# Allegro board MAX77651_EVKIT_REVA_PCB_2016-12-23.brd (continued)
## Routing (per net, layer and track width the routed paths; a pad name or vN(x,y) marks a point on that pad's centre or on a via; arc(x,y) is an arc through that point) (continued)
VBATT: length 4.3
  TOP w0.152: 46.89,40.22 U1.E3
  TOP w0.254: 46.89,40.22 46.89,40.14 46.37,39.61 46.23,39.61 v3(46.21,39.64) 46.21,39.61 46.26,39.56 C7.2 46.18,39.19 46.05,39.31 46.05,39.36 v3(46.08,39.39)
  TOP w0.381: 47.87,7.5 C15.1 v2(47.18,7.55) 47.18,7.26 ; v2(47.19,6.99) 47.19,7.1 ; v2(47.78,6.91) 47.79,6.91
  INTERNAL2 w0.254: v4(45.75,38.97) 45.8,39.01 46.09,39.07 46.08,39.07 v3(46.07,39.08) 46.1,39.08 46.23,39.2 46.23,39.26 46.19,39.29 46.18,39.29 v3(46.08,39.39)
  vias: v3(46.38,39.19) v4(45.49,38.61)
VSS: length 94.3
  TOP w0.381: C272.2 45.46,90.58 45.11,90.93 43.36,90.93 v2(42.47,90.04) ; C272.2 45.72,90.23 46.04,89.91 U211.1 ; C272.2 45.48,90.21 C271.2
  INTERNAL3 w0.254: v1(62.08,39.24) 62.08,39.34 62.05,39.37
  INTERNAL3 w0.381: v1(63.14,30.53) 62.51,30.53 62.08,30.96 v1(62.08,39.24) ; v1(62.05,71.91) v1(62.05,66.07) v1(62.05,49.96) 62.05,39.37 ; v2(42.47,90.04) v2(42.47,71.88)
  BOTTOM w0.254: U201.4 62.66,38.55 C275.2 62.73,38.84 62.33,39.24 v1(62.08,39.24)
  BOTTOM w0.381: U203.4 62.64,65.14 C277.2 62.48,65.64 v1(62.05,66.07) ; U200.4 62.74,48.25 C274.2 62.81,49.29 62.81,49.58 62.43,49.96 v1(62.05,49.96) ; v1(62.05,71.91) 60.46,71.91 60.44,71.88 v2(42.47,71.88) ; v1(63.14,30.53) 62.75,30.53 C276.2 62.72,30.49 U202.4
AMUX: length 165.5
  TOP w0.152: AMUX.1 13.22,21.49 13.29,21.41 v2(15.44,21.41) ; U1.C1 45.87,41.45 45.21,42.11 v2(15.44,42.11) 14.5,42.11 14.41,42.21 12.8,42.21 10.32,39.74 J2.2
  TOP w0.254: v2(78.78,71.05) v2(83.3,71.05)
  INTERNAL3 w0.152: v2(15.44,21.41) v2(15.44,42.11)
  INTERNAL3 w0.254: v2(15.44,42.11) 15.44,42.72 15.58,42.86 15.58,62.42 15.56,62.49 15.56,64.73 16.58,65.75 v1(16.58,70.58)
  BOTTOM w0.254: v2(83.3,71.05) 83.38,71.14 R285.1 ; v1(16.58,70.58) 35.02,70.58 35.49,71.05 v2(78.78,71.05)
BST: length 5
  TOP w0.254: v2(50.77,38.84) 50.85,38.76 50.85,38.33 C4.1
  INTERNAL2 w0.254: v3(47.69,41.45) 48.06,41.45 48.21,41.3 v4(48.26,41.3)
  INTERNAL3 w0.254: v4(48.26,41.3) v1(48.72,41.3)
  BOTTOM w0.254: v2(50.77,38.84) 50.34,39.27 50.34,39.68 v1(48.72,41.3)
CHGIN: length 8.3
  TOP w0.152: U1.E1 45.78,40.34 45.53,40.34 45.52,40.36
  TOP w0.254: v3(44.68,40.54) 44.79,40.43 C2.2 45.52,40.36
  TOP w0.381: J1.1 38.79,6.69 39.32,7.21
  TOP w1.27: 39.32,7.21 40.54,8.43 40.54,8.52 40.57,8.56 CHGIN.1
  INTERNAL2 w0.254: v3(44.68,40.54) 44.68,40.28 44.48,40.08 ; v4(44.36,39.97) 44.45,40.05
  vias: v3(44.99,40.54) v4(43.89,39.98)
CTSN: length 20.5
  TOP w0.254: U100.39 17.85,88.62 17.86,88.62 v2(18.52,88.62) ; U101.8 11.51,77.68 11.07,78.11 v2(11.07,80.5)
  INTERNAL3 w0.254: v2(18.52,80.48) v2(18.52,88.62)
  BOTTOM w0.254: v2(18.52,80.48) 17.85,80.48 17.83,80.5 v2(11.07,80.5)
DCDN: length 7.6
  TOP w0.254: v2(11.81,79.28) 11.81,78.41 12.01,78.21 U101.7 ; U100.25 14.7,81.07 13.41,79.78 13.41,79.64 13.07,79.3 v2(13.07,79.28)
  BOTTOM w0.254: v2(11.81,79.28) v2(13.07,79.28)
DSRN: length 6.2
  TOP w0.254: U101.6 12.51,79.56 14.2,81.26 U100.24
DTRN: length 8.5
  TOP w0.254: v2(16.26,81.94) 16.26,82.82 U100.28 ; v2(17.2,76.35) 16.92,76.08 U101.31
  INTERNAL3 w0.254: v2(16.26,81.94) 16.26,81.76 17.2,80.82 v2(17.2,76.35)
GPIO: length 72.9
  TOP w0.152: J2.3 4.11,37.2 4.13,37.21 12.03,37.21 ; 12.03,37.21 12.01,37.23 GPIO.1 ; 12.03,37.21 v2(14.81,37.21) ; v2(14.66,42.87) 15.52,42.87 15.87,42.52 45.35,42.52 46.02,41.85 U1.B1
  INTERNAL3 w0.152: v2(14.66,42.87) 14.66,37.92 14.81,37.77 v2(14.81,37.21) 14.81,17.98 J3.2
GROUND: length 135.1
  TOP w0.152: 47.69,40.49 U1.E5 ; U1.B3 v3(46.89,41.45) ; U206.A3 77.97,8.37 v2(78.22,8.62) ; C224.2 v2(79,6.29)
  TOP w0.254: v2(13.23,81.05) 13.46,81.28 C150.2 13.7,81.87 U100.23 ; U101.4 13.51,78.29 v2(13.23,78.56) ; C115.1 23.04,84.21 23.03,84.2 22.22,84.2 C120.1 v2(22.21,84.8) ; U103.2 33.38,86.19 33.62,85.96 C110.1 v2(34.48,85.2) ; v2(50.04,7.85) 49.56,7.85 49.26,7.55 C15.2 ; U101.24 v2(15.63,72.33) ; C153.1 19.4,90.35 v2(19.1,90.64) 18.72,91.02 C152.1 18.88,91.92 Y101.2 ; Q101.2 41.17,45.32 R137.2 ; C108.1 v2(10.81,70.73) ; v2(49.86,81.43) 49.67,81.24 C14.1 ; v2(9.45,70.54) C154.1 8.65,69.7 R115.2 ; C129.1 v2(37.33,45.71) ; 51.35,87.89 C273.1 ; C158.1 v2(28.31,90.21) 28.32,90.22 28.64,89.9 R159.2 ; v2(21.69,89.28) 21.59,89.18 21.34,89.18 21.04,88.89 C151.2 ; U100.4 7.72,88.62 v2(7.59,88.75) 7.96,89.12 U100.3 ; R138.2 36.25,45.24 Q100.2 ; U104.2 39.96,85.83 ; U100.35 18.87,86.62 v2(19.13,86.36) ; U107.13 U107.5 23.73,77.28 v2(23.39,76.94) ; R161.2 34.93,89.99 v2(34.49,90.42) 34.45,90.38 C111.1 ; U211.4 51.23,88.01 ; 49.98,39.73 49.98,40.11 C6.1 ; U101.17 v2(10.73,72.33) 10.68,72.28 C156.1 9.52,72.3 C155.2 ; C1.1 48.63,39.57 48.33,39.86 48.22,39.86 47.69,40.39 47.69,40.49 ; 40.03,85.67 40.25,85.45 C112.1 ; C134.1 v2(42.27,45.82) ; U101.20 v2(13.01,71.45) ; RT1.2 v2(24.44,6.05) ; Y101.4 v2(23.12,94.12) ; C113.1 40.5,90.38 R157.2 ; U102.2 27.44,85.75 27.69,85.51 C118.1 v2(28.49,85.26) ; C159.2 16.15,78.66 v2(16.05,78.56) ; U101.26 v2(16.86,73.58) ; SW1.4 v2(2.52,47.53) ; v2(7.52,90.65) 8.05,90.12 U100.1 ; R13.2 v2(20.04,7.13)
  TOP w0.381: v3(50.15,41.68) 50.06,41.77 C9.1 50.06,41.82 C8.1 ; 49.99,43.29 49.99,43.36 C5.1 50.09,43.44 50.18,43.53 v2(50.44,43.53) ; J6.5 v2(7.95,76.38) ; U108.2 v2(43.47,80.48) ; U108.5 v2(49.86,81.43) ; v2(23.94,89.59) 23.92,89.56 R110.2 ; C113.1 39.75,90.01 v2(39.96,89.81) ; C12.1 44.5,44.37 v2(44.47,44.41) ; C239.1 v2(85.22,49.28) ; C242.1 85.01,62.02 ; R122.2 v2(8.82,76.41) ; C241.1 84.55,33.56
  TOP w0.508: SW2.3 v2(1.11,57.78)
  TOP w0.635: C114.2 8.84,77.61 R122.2
  INTERNAL2 w0.102: 46.78,42.09 46.78,41.66 46.89,41.55 v3(46.89,41.45)
  BOTTOM w0.127: 85.6,34.98 85.6,35.39 85.48,35.51 85.04,35.51 83.57,34.04 80.27,34.04 79.79,34.52 78.9,34.52 R243.2 ; R230.2 79.31,42.03 80.05,41.29 83.55,41.29 84.68,42.42 85.25,42.42 85.34,42.33 R233.2 ; R211.2 85.35,50.62 85.28,50.69 84.65,50.69 83.09,49.14 R208.2 ; R258.2 85.22,63.43 85.21,63.43 85.17,63.47 84.25,63.47 83.48,62.7 R255.2
  BOTTOM w0.254: C223.1 v2(66.41,71.97) ; v2(61.23,80.95) U205.8 U205.9 ; v2(76.44,74.24) C205.1 77.56,74.48 R213.2 ; C249.1 v1(84.72,72.82) ; 84.73,83.93 84.8,83.86 C237.1 v2(86.62,83.86) ; 84.73,83.93 R282.2 84.73,82.87 84.12,82.26 U209.15 ; 84.73,83.93 C238.1 ; C228.1 v1(78.8,71.97) ; U205.4 63.82,73.48 63.48,73.13 v2(63.48,72.83) ; C248.1 61.01,38.63 C275.1 ; R257.1 v2(91.18,67.03) ; R210.1 v2(91.76,53.12) ; C222.1 v2(59.62,73.42)
  BOTTOM w0.381: v2(85.22,49.28) 85.22,49.88 R211.2 ; v2(87.5,74.02) 87.95,73.56 C234.1 88.69,73.57 C235.1 ; v2(94.89,73.61) 94.82,73.54 U210.2 ; C277.1 61.49,65.2 C251.1 60.84,65.92 v2(60.86,65.94) ; R244.1 92.94,38.48 93.31,38.85 ; U207.2 80.44,13.46 80.73,13.75 R268.2 81.95,13.75 C227.2 81.97,14.83 C236.1 v2(82.16,15.64) ; C276.1 61.44,30.12 v2(61.44,29.84) 61.43,29.84 ; 61.05,30.38 C250.1 ; v2(86.12,76.62) 86.09,76.59 C244.1 ; v2(91.24,42.51) 91.21,42.55 R231.1 ; C226.2 v2(77.02,16.14) ; R287.2 93.99,78.24 v2(93.93,78.18)
  BOTTOM w0.508: Q206.2 v2(93.93,78.18)
  vias: v2(2.55,44.65) v2(2.84,10.87) v2(2.95,15.44) v2(3.15,82.91) v2(3.25,67.97) v2(7.72,94.18) v2(8.53,1.83) v2(13.51,1.93) v2(16.46,94.59) v2(17.7,43.26) v2(20.74,18.41) v2(26.62,1.93) v2(27.84,8.23) v2(27.84,7.52) v2(28.55,8.23) v2(28.55,7.52) v2(29.9,12.19) v2(29.9,11.48) v2(30.61,12.19) v2(30.61,11.48) v2(35.51,7.52) v2(35.51,6.81) v2(36.22,7.52) v2(36.22,6.81) v2(38,93.78) v2(43.17,36.65) v2(43.17,36.06) v2(43.2,35.41) v2(43.76,36.66) v2(43.77,36.04) v2(43.77,35.41) v2(44.17,90.2) v2(44.2,88.95) v2(44.32,86.33) v2(45.86,47.49) v2(45.86,46.89) v2(45.88,46.25) v2(46.47,47.51) v2(46.48,46.87) v2(46.45,46.27) v2(46.53,2.24) v2(49.3,47.41) v2(49.3,46.81) v2(49.3,46.19) v2(49.92,47.44) v2(49.92,46.79) v2(49.9,46.19) v2(50.04,7.32) v2(50.7,7.85) v2(50.7,7.32) v2(52.53,2.24) v2(52.55,87.91) v2(54.83,14.54) v2(54.9,13.06) v2(56.91,8.16) v2(58.14,8.16) v2(58.57,42.11) v2(59.74,93.98) v2(60.81,49.94) v2(60.78,40.64) v2(61.41,14.79) v2(61.36,8.27) v2(61.46,13.67) v2(62.64,14.79) v2(62.59,8.27) v2(62.7,13.68) v2(63.68,66.52) v2(63.68,50.47) v2(64.47,40.74) v2(64.62,2.24) v2(64.85,13.56) v2(64.84,11.87) v2(64.92,34.44) v2(65.1,29.03) v2(65.13,26.39) v2(65.23,50.8) v2(65.23,49.68) v2(65.97,13.55) v2(66.14,68.88) v2(66.07,11.87) v2(68.25,44.4) v2(68.33,60.83) v2(68.44,43.22) v2(68.42,41.89) v2(68.73,34.54) v2(68.91,26.44) v2(69.65,41.89) v2(69.67,43.22) v2(70.82,41.66) v2(71.32,41.05) v2(71.63,61.57) v2(71.63,60.86) v2(71.83,40.64) v2(71.83,33.17) v2(71.97,58.13) v2(71.97,57.21) v2(72.14,2.13) v2(72.44,60.86) v2(73.21,58.13) v2(73.21,57.21) v2(73.86,61.47) v2(73.99,33.5) v2(74.47,41.15) v2(74.68,61.47) v2(74.75,33.5) v2(74.88,49.28) v2(74.98,41.66) v2(75.13,35.69) v2(75.13,34.87) v2(75.13,34.11) v2(75.18,62.69) v2(75.18,61.98) v2(75.29,50.5) v2(75.29,49.78) v2(75.29,42.27) v2(76.42,3.13) v2(76.42,2.57) v2(76.61,82.8) v2(76.71,79.76) v2(77.19,3.13) v2(77.21,2.58) v2(78.84,84.23) v2(80.67,70.41) v2(80.67,68.17) v2(81.48,61.26) v2(81.58,57.71) v2(81.58,53.75) v2(81.66,40.51) v2(82.6,2.54) v2(84.04,20.84) v2(85.09,62.1) v2(85.27,20.84) v2(85.85,49.28) v2(85.98,63.12) v2(85.98,62.48) v2(85.98,49.91) v2(85.98,42.24) v2(85.98,41.63) v2(86.23,35.05) v2(86.23,34.42) v2(86.66,54.05) v2(86.87,2.54) v2(86.97,94.08) v2(87.07,67.16) v2(92.86,58.72) v2(93.34,38.89) v2(93.98,47.96) v2(93.98,38.91) v2(93.98,24.28) v2(93.98,14.63) v2(94.18,9.35) v3(43.2,40.65) v3(43.18,40.35) v3(43.2,40.04) v3(43.55,41.45) v3(43.52,40.64) v3(43.5,40.34) v3(44.93,38.11) v3(44.92,37.8) v3(45.21,38.09) v3(45.21,37.81) v3(45.49,38.1) v3(45.5,37.8) v3(46.01,38.37) v3(46.01,38.07) v3(46.33,38.39) v3(46.33,38.09) v3(46.34,37.8) v3(46.64,38.39) v3(46.64,38.09) v3(49.05,39.66) v3(49.05,39.33) v3(49.04,39.03) v3(49.36,39.68) v3(49.38,39.33) v3(49.39,39.03) v3(49.68,39.68) v3(49.68,39.34) v3(49.99,39.69) v3(50,39.34) v3(50.15,41.96) v3(50.08,41.13) v3(50.08,40.79) v3(50.33,41.1) v3(50.33,40.77) v3(50.34,40.39) v3(50.34,40.06) v3(50.65,41.09) v3(50.65,40.77) v3(50.67,40.4) v3(50.69,40.06) v3(77.53,7.97)
IBATT: length 3.5
  BOTTOM w0.254: U209.7 80.95,73.23 80.54,72.81 R269.2 80.31,71.98 C228.2
IBATT_SNS: length 3.3
  TOP w0.127: v2(76.55,7.53) 77.1,7.53 U206.C1
  BOTTOM w0.127: R261.1 74.64,8.01 74.73,7.92 76.17,7.92 v2(76.55,7.53)
IBATT_SNS_RNG: length 118.5
  TOP w0.152: U206.A2 77.53,9.34 77.63,9.44 R284.2 v2(79.74,10.02)
  INTERNAL3 w0.152: v2(77.09,88.49) 77.09,73.41 76.54,72.86 76.54,26.73 79.74,23.54 v2(79.74,10.02) v2(79.74,5.52)
  INTERNAL3 w0.254: J100.5 v2(53.72,88.47)
  BOTTOM w0.152: v2(77.09,88.49) 54.3,88.49 54.27,88.47 v2(53.72,88.47)
  BOTTOM w0.254: v2(79.74,5.52) 79.66,5.44 Q204.1
IN_SBB: length 8.2
  TOP w0.152: 47.29,40.5 U1.E4
  TOP w0.254: v3(47.29,39.32) 47.29,39.33 47.29,40.5 ; v3(47.29,39.32) 47.27,39.32 47.25,39.31 v3(47.05,39.48) ; v3(47.29,39.32) 47.05,39.56 47.25,39.62 v3(47.27,39.67)
  TOP w0.381: IN_SBB.1 v2(51.77,13.05)
  INTERNAL2 w0.254: 47.29,39.35 47.29,39.39 47.22,39.5 v3(47.27,39.67) ; 47.29,39.35 v3(47.29,39.32) ; 47.29,39.35 v3(47.05,39.16) ; v3(47.05,39.48) 47.08,39.18 v3(47.05,39.16) ; v3(47.05,39.16) 47.05,39.12 47.05,39.13 46.75,39.43 46.75,39.66 46.73,39.69 v4(46.69,39.7)
  INTERNAL3 w0.254: v4(47,40.01) 46.82,39.77 v4(46.69,39.7) 47.02,39.7 47.17,39.55 47.17,39.47 v1(47.09,39.39)
  BOTTOM w0.254: v1(47.09,39.39) 47.12,39.42 47.67,39.42 v1(47.64,39.39)
  vias: v2(49.81,14) v2(49.81,13.06) v2(50.77,13.94) v2(50.8,13.03) v2(51.77,14) v2(52.86,13.06)
INLDO: length 36.8
  TOP w0.152: U1.B6 48.25,41.85 48.32,41.92
  TOP w0.254: 48.81,42.45 48.32,41.96 48.32,41.92
  TOP w0.381: R11.1 51.08,42.62 v2(51.4,42.93) ; C18.2 74.97,53.73 74.98,53.72 ; C13.1 49.11,42.59 48.95,42.59 48.81,42.45
  TOP w1.016: 52.2,44.07 51.4,43.27 v2(51.4,42.93)
  TOP w1.27: 52.2,44.07 61.85,53.72 76.37,53.72 76.41,53.69 INLDO.1
  INTERNAL2 w0.381: v3(49.06,42.64) 49.07,42.63 v4(49.41,42.63)
  INTERNAL3 w0.508: v2(51.4,42.93) 51.09,42.63 v4(49.41,42.63)
ISET_LDO: length 11.7
  INTERNAL3 w0.254: v2(59.66,72.67) v2(59.66,66.24)
  BOTTOM w0.254: U205.6 62.52,73.65 61.55,72.67 v2(59.66,72.67) ; v2(59.66,66.24) 59.66,65.54 R250.1
ISET_SBB0: length 30.8
  INTERNAL3 w0.254: v1(59.87,52.89) 59.87,52.15 59.88,52.13 v1(59.88,49.98) ; v1(65.12,73.29) v1(65.12,52.89)
  BOTTOM w0.254: v1(65.12,52.89) v1(59.87,52.89) ; U205.2 v1(65.12,73.29) ; R203.1 v1(59.88,49.98)
ISET_SBB1: length 40.6
  INTERNAL3 w0.254: v1(59.92,42.55) v1(59.92,39.45) ; v1(64.47,72.55) v1(64.47,42.55)
  BOTTOM w0.254: R224.1 59.92,38.83 v1(59.92,39.45) ; U205.3 v1(64.47,72.55) ; v1(64.47,42.55) v1(59.92,42.55)
ISET_SBB2: length 47
  INTERNAL3 w0.254: v1(62.74,73.11) v1(62.74,31.22)
  BOTTOM w0.254: v1(62.74,73.11) 63.17,73.54 U205.5 ; R237.1 59.8,30.72 60.3,31.22 v1(62.74,31.22)
LDO: length 96.3
  TOP w0.254: 73.54,59.48 73.13,59.88 C17.2
  TOP w0.381: 50.38,45.04 50.07,45.04 49.16,44.13 C5.2
  TOP w1.27: J207.2 85.58,58.92 85.57,58.91 83.8,58.91 83.24,59.48 LDO.1 64.81,59.48 50.38,45.04
  INTERNAL2 w0.254: v3(49.09,43.45) 48.58,43.45 48.25,43.12 48.25,42.41 v3(47.69,41.85)
  INTERNAL3 w0.381: v2(76.83,92.56) 77.8,91.59 77.8,69.29 78.41,68.68 LDO.1
  BOTTOM w0.381: v2(76.83,92.56) 62.94,92.56 J101.6
LED0: length 19
  TOP w0.152: 48.39,43.03 48.39,42.55 U1.A6
  TOP w0.229: 49.19,57.54 R7.2
  TOP w0.254: LED0.1 48.22,57.54 49.19,57.54 ; v2(48.57,44.97) 48.57,43.74 48.39,43.56 48.39,43.03
  INTERNAL3 w0.305: 48.26,57.56 48.2,57.56 LED0.1
  INTERNAL3 w0.356: v2(48.57,44.97) 48.57,45.1 48.56,45.1 48.56,57.25 48.26,57.56
LED1: length 19
  TOP w0.152: 47.99,42.97 48,42.96 48,42.56 U1.A5
  TOP w0.254: v2(47.83,45.7) 47.83,43.59 47.99,43.42 47.99,42.97
  TOP w0.33: R8.2 48.36,56.18 48.33,56.15 LED1.1
  INTERNAL3 w0.305: LED1.1 47.73,54.73 47.73,46.44 47.83,46.34 v2(47.83,45.7)
LED2: length 18.2
  TOP w0.152: U1.A4 47.65,42.61 47.65,43.01 47.58,43.08
  TOP w0.254: v2(47.09,44.78) 47.09,43.57 47.58,43.08
  TOP w0.381: R6.2 46.39,54.95 LED2.1
  INTERNAL3 w0.279: 47.09,52.6 v2(47.09,44.78)
  INTERNAL3 w0.305: 47.09,52.6 47.09,52.72 LED2.1
LXA: length 3.6
  TOP w0.254: v3(47.59,38.06) 47.5,38.06 47.46,38.09 ; v3(47.31,38.36) 47.46,38.21 47.46,38.09 ; 47.46,38.09 47.61,38.24 v3(47.61,38.36) ; 47.46,38.09 47.34,38.09 v3(47.31,38.07)
  INTERNAL2 w0.254: 47.46,40.41 47.29,40.58 v3(47.29,41.05)
  INTERNAL2 w0.508: 47.46,40.41 47.84,40.03 47.84,38.6
LXB: length 3.6
  TOP w0.254: v3(48.6,38.05) 48.65,38.09 48.88,38.09 v3(48.94,38.04) ; v3(48.93,38.38) 48.8,38.25 48.8,38.18 v3(48.6,38.38)
  INTERNAL2 w0.254: 48.05,40.69 v3(47.69,41.05)
  INTERNAL2 w0.508: 48.05,40.69 48.48,40.26 48.48,38.7
MAXQP03: length 1.8
  TOP w0.254: U100.52 11.7,91.82 11.56,91.96 PO3.1
MAXQP05: length 2
  TOP w0.254: PO5.1 10.06,92.05 10.7,91.4 U100.54
NEN: length 81.4
  TOP w0.152: U1.A2 45.46,43.28 22.35,43.28 20.02,45.62 v2(19.41,45.62) ; J2.5 8.87,32.12 8.92,32.07 v2(9.47,32.07)
  TOP w0.254: J5.2 11.3,60.06 10.87,59.64 10.16,59.64 10.13,59.61 v2(9.52,59.61) ; v2(19.41,45.62) v2(9.45,45.62)
  INTERNAL3 w0.152: NEN.1 19.47,46.34 19.41,46.28 v2(19.41,45.62) ; v2(9.52,59.61) 9.52,45.72 ; 9.52,45.72 9.52,32.68 9.47,32.63 v2(9.47,32.07) ; 9.52,45.72 9.45,45.65 v2(9.45,45.62)
NIRQ: length 93.5
  TOP w0.152: 23.44,41.14 23.42,41.12 v2(23.42,41.12) ; 23.44,41.14 v2(39.29,41.14) ; 23.44,41.14 v2(13.24,41.14) ; NIRQ.1 9.54,29.58 J2.6 ; v2(19.82,76.81) 19.84,76.79 R14.1
  TOP w0.254: v2(19.82,76.81) 19.17,77.46 R150.2
  INTERNAL2 w0.152: v3(46.49,41.45) 46.1,41.45 v4(46,41.56)
  INTERNAL3 w0.152: NIRQ.1 13.24,33.28 v2(13.24,41.14) ; v2(39.29,41.14) 40.57,42.42 45.77,42.42 46,42.19 v4(46,41.56) ; v2(23.42,41.12) 23.42,59.87 19.82,63.47 v2(19.82,76.81)
NIRQ1: length 28.8
  TOP w0.254: R152.1 v2(28.29,81.68) ; U100.49 13.2,91.7 13.77,92.26 13.77,93.38 PO0.1
  INTERNAL3 w0.254: v2(28.29,81.68) 28.29,84.18 26.92,85.55 26.92,91.44 25.83,92.53 v2(25.83,93.5)
  BOTTOM w0.254: PO0.1 25.19,93.53 25.22,93.5 v2(25.83,93.5)
NRST: length 68.6
  TOP w0.152: v2(14,41.68) 14.55,41.68 14.57,41.66 v2(40.87,41.66)
  TOP w0.254: R10.1 10.73,27.02 10.74,27.04 ; 10.74,27.04 10.8,27.09 NRST.1 13.16,27.09 13.2,27.06 v2(14,27.06) ; 10.74,27.04 J2.7
  INTERNAL2 w0.152: 46.49,41.85 46.37,41.97 v4(45.56,41.97)
  INTERNAL2 w0.254: v3(46.49,41.85) 46.49,41.85
  INTERNAL3 w0.152: v4(45.56,41.97) 41.74,41.97 41.43,41.66 v2(40.87,41.66) ; v2(14,41.68) v2(14,27.06)
  INTERNAL3 w0.254: v2(14,41.68) 14,42.29 13.92,42.36 13.92,49.41 13.91,49.42 J8.1
P01: length 146.6
  TOP w0.152: v2(71.07,10.07) 76.72,10.07 76.78,10.02 R284.1
  TOP w0.254: U100.50 12.7,92.38 PO1.1
  INTERNAL3 w0.254: v1(71.07,16.64) v2(71.07,10.07) ; v2(26.21,18.54) 26.21,91.14 25.09,92.26 v1(25.09,92.66)
  BOTTOM w0.254: v2(26.21,18.54) 26.82,18.54 26.85,18.52 55.98,18.52 57.86,16.64 v1(71.07,16.64) ; PO1.1 v1(25.09,92.66)
P02: length 2.6
  TOP w0.254: U100.51 12.2,92.8 12.19,92.81 PO2.1
P04: length 2.8
  TOP w0.254: U100.53 11.2,91.77 10.79,92.18 10.79,92.67 10.67,92.79 PO4.1
P06: length 3
  TOP w0.254: PO6.1 9.38,92.78 9.35,92.75 9.35,92.08 10.2,91.22 U100.55
P07: length 2.2
  TOP w0.254: PO7.1 8.69,92.18 9.7,91.17 U100.56
PWRHLD: length 96.8
  TOP w0.152: J2.4 v2(10.66,34.66) ; U1.A1 45.42,42.93 20.62,42.93 PWRHLD.1 14.05,44.06 12.48,42.49 10.87,42.49 10.85,42.47 v2(10.67,42.47)
  TOP w0.254: v2(10.82,56.75) R16.2
  INTERNAL3 w0.152: v2(10.82,56.75) 10.82,56.19 10.67,56.03 v2(10.67,42.47) 10.67,34.75 ; 10.67,34.75 10.66,34.74 v2(10.66,34.66) ; 10.67,34.75 10.67,10.36 11.89,9.14 J4.2
REF_1: length 76
  INTERNAL3 w0.254: v2(89.71,13.77) 89.71,56.79 90.22,57.3 90.22,70.15 88.24,72.14 v2(88.24,76.3)
  BOTTOM w0.254: R279.2 87.44,75.58 86.92,75.06 86.11,75.06 C244.2 85.46,75.08 85.46,75.08 U209.1
  BOTTOM w0.381: v2(88.24,76.3) 88.23,76.29 R279.2 ; C236.2 R265.1 88.42,13.71 88.47,13.77 v2(89.71,13.77)
RIN: length 6.2
  TOP w0.254: U100.27 15.7,81.97 15.7,81.96 15.7,81.28 14.01,79.59 U101.3
RTSN: length 7.5
  TOP w0.254: v2(15.21,81.61) 15.21,82.86 U100.26 ; v2(16.51,76.78) 16.3,76.58 U101.32
  INTERNAL3 w0.254: v2(15.21,81.61) 16.61,80.21 16.61,77.5 16.51,77.39 v2(16.51,76.78)
RXD: length 15.5
  TOP w0.254: v2(16.92,91.05) 16.74,90.87 U100.43 ; v2(16.92,81.84) 14.5,79.43 14.5,78.33 14.51,78.33 U101.2
  INTERNAL3 w0.254: v2(16.92,81.84) v2(16.92,91.05)
SBB0: length 40.8
  TOP w0.152: 48.27,41.45 U1.C6
  TOP w0.254: 48.27,41.45 48.44,41.45 48.78,41.8 49.14,41.8 C9.2
  TOP w0.381: v2(51.97,41.73) 51.96,41.72 R11.2
  TOP w0.508: 53.09,42.42 53.09,42.11 52.71,41.73 v2(51.97,41.73)
  TOP w1.27: 80.49,46.08 SBB0.1 56.73,46.06 53.09,42.42 ; J201.2 80.53,46.11
  INTERNAL2 w0.254: 49.28,41.85 v3(49.18,41.95) ; 49.5,41.7 v4(49.6,41.7) 49.54,41.64 ; v3(49.16,41.66) 49.18,41.64
  INTERNAL3 w0.508: v2(51.97,41.73) 51.24,41.73 51.21,41.71 50.7,41.71 50.7,41.7 v4(49.6,41.7)
SBB1: length 38.9
  TOP w0.152: 48.27,41.05 U1.D6
  TOP w0.254: 48.27,41.05 48.97,41.05 49.08,40.94 49.13,40.94 C8.2
  TOP w0.508: 53.47,40.89 v2(51.44,40.89)
  TOP w1.27: 53.47,40.89 56.27,40.89 58.41,38.74 SBB1.1 83.88,38.74 84.05,38.91 85.81,38.91 ; J203.2 85.8,38.93
  INTERNAL2 w0.254: 49.47,40.83 v4(49.52,40.89) 49.38,41.03 ; v3(49.25,40.86) 49.28,40.83 ; v3(49.05,41.05) 49.07,41.03
  INTERNAL3 w0.508: v4(49.52,40.89) v2(51.44,40.89)
SBB2: length 43.1
  TOP w0.152: 48.23,40.52 48.1,40.65 U1.E6
  TOP w0.254: 49.13,40.21 C6.2 ; 48.23,40.52 48.55,40.21 49.13,40.21 49.08,40.25
  TOP w0.508: v2(52.16,40.15) 52.18,40.15 53.21,39.12
  TOP w1.27: J205.2 84.26,31.44 ; SBB2.1 84.07,31.55 84.11,31.59 85.87,31.59 ; SBB2.1 78.37,31.54 ; SBB2.1 60.78,31.55 53.21,39.12
  INTERNAL2 w0.254: 49.47,40.33 v4(49.65,40.15) 49.63,40.13 ; v3(49.25,40.08) 49.3,40.13 ; v3(49.05,40.28) 49.1,40.33
  INTERNAL3 w0.508: v4(49.65,40.15) v2(52.16,40.15)
SCL: length 116.8
  TOP w0.127: C134.2 43.32,47.31 43.32,47.3 43.88,47.3 46.53,44.65 46.53,43.62 47.29,42.86 v3(47.29,42.68)
  TOP w0.152: v2(22.5,49.86) 37.97,49.86 39.46,48.38 Q101.3 ; v2(16.1,24.5) 15.49,24.5 15.49,24.5 J2.8
  TOP w0.254: SCL.1 18.17,61.69 18.12,61.73 v2(16.24,61.73) ; Q101.3 41.7,48.38 42.19,47.89 42.19,47.39 C134.2 ; R107.2 19.16,79.82 R136.2 v2(18.51,79.82)
  INTERNAL2 w0.152: v3(47.29,42.68) 47.29,42.59 v3(47.29,41.85)
  INTERNAL3 w0.152: v2(16.1,24.5) 16.1,60.99 16.24,61.13 v2(16.24,61.73) 16.24,64 18.51,66.26 v2(18.51,79.82) ; SCL.1 22.5,58.53 v2(22.5,49.86)
SCL1: length 100.5
  TOP w0.254: R162.1 34.1,81.47 32.66,82.91 v2(25.65,82.91) 25.65,81.28 25.63,81.26 U107.9 ; R155.2 v2(21.41,86.85) 21.83,86.85 R118.1
  INTERNAL3 w0.152: J100.3 48.64,92.67 49.05,92.26 49.05,87.63 49.04,87.62 49.04,87.31 49.12,87.23 v2(49.12,86.67)
  INTERNAL3 w0.203: v2(61.03,82.44) v2(61.03,86.66)
  INTERNAL3 w0.254: v2(21.41,86.85) 22.52,86.85 23.93,85.44 23.93,83.87 24.89,82.91 v2(25.65,82.91)
  BOTTOM w0.152: v2(21.41,86.85) 21.97,86.85 22.23,87.12 47.1,87.12 47.54,86.67 v2(49.12,86.67) 63.16,86.67 63.18,86.69 79.96,86.69 80.67,87.4 81.1,87.4 81.12,87.42 R304.1
  BOTTOM w0.203: R305.1 v2(61.03,82.44) ; 60.78,86.67 60.8,86.66 v2(61.03,86.66)
SDA: length 112.7
  TOP w0.127: U1.A3 46.87,42.25 46.76,42.36 46.76,42.36 46.65,42.48 46.65,42.49 45.25,43.89 39.01,43.89 38.17,44.73 38.17,46.9 37.9,47.17 C129.2
  TOP w0.152: v2(16.97,48.3) 17.53,48.3 17.55,48.28 Q100.3 ; v2(16.97,56.2) 18.35,56.2 18.36,56.19 SDA.1 ; J2.9 3.76,22.81 16.38,22.81 16.41,22.84 v2(16.97,22.84)
  TOP w0.254: v2(19.19,82.03) R108.2 19.18,81.31 R135.2 ; Q100.3 36.93,48.28 37.34,47.87 37.34,47.18 C129.2
  INTERNAL3 w0.152: v2(19.19,82.03) 19.19,65.5 16.97,63.27 v2(16.97,56.2) v2(16.97,48.3) v2(16.97,22.84)
SDA1: length 101.9
  TOP w0.254: U107.10 v2(24.53,84.2) 25.24,83.49 33.22,83.49 34.33,82.38 v2(40.89,82.38) ; R148.2 v2(21.41,87.67) 21.81,87.67 R100.1 ; R164.2 v2(40.89,79.52)
  INTERNAL3 w0.152: J100.4 v2(51.18,87.17)
  INTERNAL3 w0.203: v2(61.7,83.3) v2(61.7,87.16)
  INTERNAL3 w0.254: v2(24.53,84.2) 24.53,85.75 22.61,87.67 v2(21.41,87.67) ; v2(40.89,79.52) v2(40.89,82.38)
  BOTTOM w0.152: R303.1 81.12,88.3 81.1,88.29 80.75,88.29 79.63,87.17 v2(51.18,87.17) 47.65,87.17 46.98,87.85 22.15,87.85 21.97,87.67 v2(21.41,87.67)
  BOTTOM w0.203: R306.1 v2(61.7,83.3) ; v2(61.7,87.16) 61.55,87.16 61.54,87.17
THM: length 55.3
  TOP w0.254: v2(40.88,39.84) 40.45,39.41 21.43,39.41 THM.1 ; J7.1 21.13,17.07 v2(17.88,17.07)
  INTERNAL2 w0.152: v3(46.49,41.05) 46.33,41.05 46.28,41 46.06,41 46.04,40.98 v4(45.89,40.98)
  INTERNAL3 w0.152: v2(40.88,39.84) 42.02,40.98 v4(45.89,40.98)
  INTERNAL3 w0.254: THM.1 17.88,35.86 v2(17.88,17.07)
THMB: length 68.2
  TOP w0.254: R15.1 23.22,7.13 R1.1 23.23,5.3 R12.1 ; v2(41.72,39.84) 40.74,38.86 26.34,38.86 TBIAS.1
  INTERNAL2 w0.254: v3(46.89,41.05) 46.89,40.86 46.52,40.49 45.82,40.49 45.8,40.47 v4(45.6,40.47)
  INTERNAL3 w0.152: v2(41.72,39.84) 42.47,40.59 44.95,40.59 45.06,40.47 v4(45.6,40.47)
  INTERNAL3 w0.254: R12.1 21.72,4.07 18.9,6.89 18.9,28.75 19.6,29.46 TBIAS.1
TXD: length 20.9
  TOP w0.254: U101.30 v2(17.82,75.58) ; v2(17.12,91.85) 15.96,91.85 15.7,91.59 U100.44
  INTERNAL3 w0.254: v2(17.82,75.58) 17.82,91.15 v2(17.12,91.85)
UNNAMED_1_10103592-0001LF_I53_SHIELD10: length 21.7
  TOP w0.762: J1.8 39.92,4.13 J1.9 41.39,2.25 J1.10 J1.11 36.36,2.45 J1.6 35.07,4.13 J1.7 32.64,5.53 31.91,6.27 R3.1 30.93,7.13 R4.1
UNNAMED_1_CL-SB-12B-1X_I99_2: length 3.3
  TOP w0.254: J5.1 7.5,61.64 7.4,61.54 SW2.2
UNNAMED_1_EKCAPNP_I55_1: length 1.3
  TOP w0.762: R3.2 29.59,7.54 C10.1
UNNAMED_1_EKCAPNP_I69_2: length 30.8
  TOP w0.254: v3(46.92,42.71) 45.85,43.78 C12.2 45.85,44.78 45.34,45.29 v2(45.14,45.29) ; R17.1 v2(36.77,66.89)
  INTERNAL2 w0.102: 46.99,41.76 v3(47.29,41.45)
  INTERNAL2 w0.127: v3(46.92,42.71) 46.99,42.55 46.99,41.76
  INTERNAL3 w0.254: v2(36.77,66.89) 36.77,53.65 v2(45.14,45.29)
UNNAMED_1_EKRESSMD_I59_1: length 2.1
  TOP w0.279: DS1.1 53.14,57.28 52.89,57.54 R7.1
UNNAMED_1_EKRESSMD_I60_1: length 2
  TOP w0.279: DS1.2 52.94,56.41 52.72,56.18 R8.1
UNNAMED_1_EKRESSMD_I61_1: length 2.2
  TOP w0.305: DS1.3 53.3,54.95 R6.1
UNNAMED_1_EKRESSMD_I72_2: length 6.7
  TOP w0.254: 57.22,56.53 57.03,56.53 56.9,56.41 DS1.5 ; 57.22,56.53 56.48,57.28 DS1.4 ; 57.22,56.53 R9.2 57.23,56.32 56.98,56.32 56.91,56.24 56.91,56.13 56.32,55.53 DS1.6
UNNAMED_1_EVKJUMPER_I94_2: length 17.1
  TOP w0.254: R12.2 23.08,1.53 23.1,1.55 24.54,1.55 25.88,2.9 25.88,8.43 25.41,8.9 J7.2
UNNAMED_1_HEADER2P_I92_2: length 3.5
  TOP w0.254: J8.2 13.91,53.48 13.92,53.49 13.92,54.38 13.94,54.39 R16.1
UNNAMED_1_HEADER3P_I78_3: length 14.5
  TOP w0.254: v2(11.63,53.92) 11.56,53.99 SW1.1 ; J5.3 13.84,60.39 13.95,60.27 R2.1
  INTERNAL3 w0.254: v2(11.63,53.92) 11.63,57.61 13.79,59.77 13.79,60.34 13.84,60.39 J5.3
UNNAMED_1_RESSMD_I44_2: length 6.3
  TOP w0.254: R1.2 24.43,8.36 RT1.1 24.44,11.22 J7.3
UNNAMED_1_RESSMD_I93_2: length 8.4
  TOP w0.254: R15.2 20.89,8.35 R13.1 20.89,9.12 20.33,9.67 J7.4
UNNAMED_2_CAPNP_I23_1: length 5.9
  BOTTOM w0.381: R265.2 83.05,12.51 C227.1 81.95,12.53 R268.1 80.17,12.53 80.15,12.51 U207.3 79,11.74 78.99,11.73 R264.2
UNNAMED_2_CAPNP_I24_1: length 5.5
  BOTTOM w0.381: R267.1 72.5,12.36 R266.1 73.5,12.38 C225.1 74.58,12.51 U207.4 76.1,11.74 76.09,11.73 R263.2
UNNAMED_2_CAPNP_I24_2: length 70.9
  INTERNAL2 w0.381: v2(79,15.28) 75.16,15.28 v2(74.43,14.55)
  INTERNAL3 w0.254: v2(74.43,14.55) 75.79,15.92 75.79,72.18 75.77,72.2 v2(75.77,72.81)
  BOTTOM w0.254: v2(74.43,14.55) 74.43,13.63 C225.2 74.44,13.58 R266.2 73.46,13.6 R267.2 ; R269.1 v2(75.77,72.81)
  BOTTOM w0.381: U207.1 v2(79,15.28)
UNNAMED_2_EKCAPNP_I56_2: length 4.9
  BOTTOM w0.381: 89.47,72.59 89.59,72.71 C234.2 ; 89.47,72.59 R277.2 ; 89.47,72.59 U210.4 91.03,71.43 91.37,71.09 R280.1
UNNAMED_2_EKCAPNP_I61_2: length 2.6
  BOTTOM w0.381: U210.5 89.62,74.49 C235.2 89.59,75.56 R279.1
UNNAMED_2_EKRESSMD_I63_2: length 2.3
  BOTTOM w0.381: R280.2 93.56,71.09 93.93,71.47 U210.3
UNNAMED_2_MAX14689_I1_COM1: length 2.6
  TOP w0.127: v2(76.1,8.36) 76.47,8.36 76.86,7.97 U206.B1
  BOTTOM w0.127: R263.1 76.09,9.25 76.1,9.24 v2(76.1,8.36)
UNNAMED_2_MAX14689_I1_COM2: length 2.6
  TOP w0.127: v2(78.97,8.37) 78.58,7.97 U206.B3
  BOTTOM w0.127: R264.1 78.99,9.27 78.97,9.26 v2(78.97,8.37)
UNNAMED_2_MAX14689_I1_NC1: length 7.3
  TOP w0.127: U206.C3 77.93,7.57 v2(77.93,7.05)
  TOP w0.152: U206.A1 v2(76.78,8.72)
  BOTTOM w0.127: R261.2 74.64,7.57 74.74,7.67 75.59,7.67 76.21,7.05 v2(77.93,7.05)
  BOTTOM w0.152: v2(76.78,8.72) 77.93,7.57 v2(77.93,7.05)
UNNAMED_4_24AA02_I200_SCL: length 2.5
  TOP w0.254: R162.2 43.34,81.47 43.37,81.43 U108.1
UNNAMED_4_24AA02_I200_SDA: length 2.4
  TOP w0.254: R164.1 43.38,79.52 43.39,79.53 U108.3
UNNAMED_4_24AA02_I200_VCC: length 2.9
  TOP w0.254: U108.4 49.65,79.53 C14.2 50.87,79.51 R163.1
UNNAMED_4_10103592-0001LF_I2_1: length 3.4
  TOP w0.381: C155.1 7.73,73.2 FB100.1 7.14,73.78 J6.1
UNNAMED_4_10103592-0001LF_I2_2: length 2
  TOP w0.254: R123.1 6.94,74.37 6.88,74.43 J6.2
UNNAMED_4_10103592-0001LF_I2_3: length 2.1
  TOP w0.254: R103.1 6.94,75.18 6.84,75.08 J6.3
UNNAMED_4_10103592-0001LF_I2_SHIELD10: length 19
  TOP w0.508: J6.8 4.27,72.66 J6.9 2.39,71.18 J6.10 J6.11 2.39,78.98 J6.6 4.27,77.51 J6.7
  TOP w0.635: R142.1 7.48,78.75 R122.1 5.76,77.6 J6.7
UNNAMED_4_CAPNP_I101_2: length 6.8
  TOP w0.254: U100.41 21.13,89.62 21.38,89.87 C153.2 21.38,91.44 Y101.3
UNNAMED_4_CAPNP_I105_2: length 6.1
  TOP w0.254: U100.42 17.25,90.12 17.75,90.62 17.75,92.63 18.01,92.89 18.63,92.89 C152.2 19.12,92.98 Y101.1
UNNAMED_4_EKCAPNP_I12_1: length 16.9
  TOP w0.254: U101.16 9.86,73.08 9.76,73.18 C156.2 9.5,73.22 9.5,73.53 9.32,73.71 v2(9.3,73.71) ; U101.1 15.01,78.29 15.25,78.53 C159.1 15.25,79.41 v2(15.72,79.89)
  INTERNAL3 w0.254: v2(10.08,79.89) 10.08,74.73 9.73,74.37 9.73,74.14 v2(9.3,73.71)
  BOTTOM w0.254: v2(15.72,79.89) v2(10.08,79.89)
UNNAMED_4_EKCAPNP_I29_1: length 1.3
  TOP w0.635: R142.2 C114.1
UNNAMED_4_EKRESSMD_I15_2: length 2.7
  TOP w0.254: R123.2 9.27,74.37 9.47,74.17 9.49,74.17 9.75,73.9 9.75,73.89 10.06,73.58 U101.15
UNNAMED_4_EKRESSMD_I16_2: length 2.8
  TOP w0.254: R103.2 9.07,75.18 10.16,74.09 10.75,74.09 U101.14
UNNAMED_4_EKRESSMD_I17_1: length 1.6
  TOP w0.254: U101.22 14.01,70.98 R111.1
UNNAMED_4_EKRESSMD_I17_2: length 1.9
  TOP w0.254: D100.K 15.02,69.71 14.81,69.92 R111.2
UNNAMED_4_EKRESSMD_I18_1: length 1.6
  TOP w0.254: U101.21 13.51,71.01 R109.1
UNNAMED_4_EKRESSMD_I18_2: length 1.9
  TOP w0.254: R109.2 12.63,69.93 12.4,69.7 D101.K
UNNAMED_4_EKRESSMD_I87_1: length 2.5
  TOP w0.254: R150.1 21.37,78.09 21.83,78.55 U107.3
UNNAMED_4_EKRESSMD_I109_1: length 3.2
  TOP w0.254: U100.36 19.2,87.12 19.46,86.85 R155.1
UNNAMED_4_EKRESSMD_I113_1: length 3.1
  TOP w0.254: U100.37 19.43,87.62 19.48,87.67 R148.1
UNNAMED_4_EKRESSMD_I149_1: length 2.6
  TOP w0.254: R141.1 34.54,46.48 Q100.1 35.3,46.43 R138.1
UNNAMED_4_EKRESSMD_I150_1: length 2.8
  TOP w0.254: R139.1 39.33,46.58 Q101.1 40.17,45.38 R137.1
UNNAMED_4_EKRESSMD_I151_2: length 25.6
  TOP w0.152: R141.2 33.56,47.78 33.54,47.75 v2(28.12,47.75)
  INTERNAL3 w0.152: v2(28.12,47.75) 28,47.87 QSDA.1
UNNAMED_4_EKRESSMD_I152_2: length 23.6
  TOP w0.152: v2(33.82,49.25) 37.51,49.25 38.79,47.97 R139.2
  INTERNAL3 w0.152: v2(33.82,49.25) 33.82,66.04 33.88,66.1 QSCL.1
UNNAMED_4_EKRESSMD_I153_1: length 1.8
  TOP w0.254: U107.1 20.9,80.71 20.77,80.57 R135.1
UNNAMED_4_EKRESSMD_I154_1: length 1.8
  TOP w0.254: R136.1 20.65,79.82 20.73,79.91 U107.2
UNNAMED_4_EKRESSMD_I171_2: length 1.6
  TOP w0.254: R143.2 24.55,76.97 24.53,76.99 U107.6
UNNAMED_4_EKRESSMD_I174_1: length 3.9
  TOP w0.254: R156.2 40.48,91.2 R157.1 40.91,91.25 41.26,90.89 41.26,89.98 40.61,89.33 U104.4
UNNAMED_4_EKRESSMD_I177_1: length 1.7
  TOP w0.254: R158.2 29.05,89.01 R159.1 29.03,88.99 U102.4
UNNAMED_4_EKRESSMD_I190_2: length 2.7
  TOP w0.254: R152.2 27.35,80.85 R151.2 26.77,79.94 26.73,79.91 U107.8
UNNAMED_4_LED_I7_B: length 1.3
  TOP w0.254: R110.1 23.92,88.21 D102.K
UNNAMED_4_LED_I189_B: length 1.8
  TOP w0.254: R151.1 29.07,79.94 29.1,79.92 D103.K
UNNAMED_4_MAX8512_I5_FB: length 2
  TOP w0.254: U103.4 35.2,89.04 R161.1 R160.2
UNNAMED_6_CAPNP_I21_1: length 28.4
  INTERNAL3 w0.254: v1(58.67,52.17) 58.67,48.66 58.53,48.52 v1(58.53,47.73) ; v1(69.87,52.17) v1(69.87,45.09)
  BOTTOM w0.254: 69.83,45.89 69.83,45.79 C203.1 69.86,45.78 69.62,46.02 69.42,46.02 69.16,46.27 69.16,46.56 68.81,46.91 U200.7 ; 69.83,45.89 70.7,45.89 R205.1 ; 69.83,45.89 69.87,45.85 v1(69.87,45.09) ; v1(58.67,52.17) 69.26,52.17 69.26,52.17 v1(69.87,52.17) ; R202.2 v1(58.53,47.73)
UNNAMED_6_CAPNP_I227_2: length 4.5
  BOTTOM w0.254: U209.12 82.22,82.07 82.21,82.08 R281.2 83.39,82.84 R282.1 83.51,83.93 C238.2
UNNAMED_6_CAPNP_I245_2: length 3.3
  BOTTOM w0.254: R285.2 82.48,71.89 C249.2 82.48,73.49 82.22,73.75 U209.5
UNNAMED_6_CAPNP_I271_2: length 16
  BOTTOM w0.127: R229.1 77.16,42.82 73.2,38.86 69.69,38.86 68.47,37.64 U201.5
  BOTTOM w0.152: 70.43,38.86 70.41,38.88 R295.1
  BOTTOM w0.254: R226.2 67.37,40.27 C208.2 67.37,38.25 67.36,38.24 U201.5
UNNAMED_6_CAPNP_I277_1: length 20.6
  INTERNAL3 w0.254: v1(58.42,37.21) 59.05,36.58 v1(59.05,33.35) ; v1(69.34,34.82) v1(69.34,33.35)
  BOTTOM w0.254: C209.1 69.35,35.64 R228.1 ; v1(69.34,33.35) v1(59.05,33.35) ; R228.1 v1(69.34,34.82) ; R228.1 69.25,35.62 68.54,36.34 U201.7 ; v1(58.42,37.21) 58.95,37.21 R223.2
UNNAMED_6_CAPNP_I277_2: length 15.2
  BOTTOM w0.127: 68.55,37 68.55,37 68.55,37.33 69.75,38.52 73.39,38.52 76.89,42.03 R230.1
  BOTTOM w0.152: 70.41,38.52 70.43,38.5 R296.2
  BOTTOM w0.254: C209.2 70.34,36.84 R228.2 69.2,36.99 68.54,36.99 ; 68.54,36.99 68.55,37 ; 68.54,36.99 U201.6
UNNAMED_6_CAPNP_I289_2: length 3.2
  BOTTOM w0.254: U201.3 61.02,36.99 60.84,37.16 C248.2 60.75,37.24 60.42,37.57 60.42,37.6 60.11,37.91 R224.2
UNNAMED_6_CAPNP_I307_2: length 15.9
  BOTTOM w0.127: 67.99,29.56 68.96,29.56 70.21,30.81 73.14,30.81 77.23,34.9 77.58,34.9 78.01,35.33 R242.1
  BOTTOM w0.152: R297.1 70.57,30.82 70.56,30.81
  BOTTOM w0.254: R240.2 67.4,30.89 C214.2 67.39,30.2 67.42,30.17 U202.5 67.99,29.56
UNNAMED_6_CAPNP_I311_1: length 24.1
  INTERNAL3 w0.254: v2(58.93,29.71) v2(58.93,24.71) ; v2(70.26,24.71) v2(70.26,26.92)
  BOTTOM w0.254: v2(58.93,29.71) 58.89,29.67 R236.2 ; v2(70.26,26.92) 70.26,27.57 C213.1 ; C213.1 71.16,27.74 R239.1 ; C213.1 69.42,27.74 69.34,27.74 68.81,28.26 U202.7 ; v2(58.93,24.71) v2(70.26,24.71)
UNNAMED_6_CAPNP_I311_2: length 15.9
  BOTTOM w0.127: 68.79,28.91 70.31,30.43 73.27,30.43 77.34,34.5 R243.1
  BOTTOM w0.152: 70.56,30.43 70.55,30.42 R298.2
  BOTTOM w0.254: 70.12,28.91 70.12,28.92 C213.2 ; 70.12,28.91 70.13,28.91 70.17,28.94 R239.2 ; 70.12,28.91 U202.6
UNNAMED_6_CAPNP_I323_2: length 3.3
  BOTTOM w0.254: U202.3 61.81,28.91 61.56,29.16 C250.2 60.81,29.16 60.55,29.41 60.55,29.41 60.47,29.49 60.47,29.49 60.27,29.69 59.85,29.69 R237.2
UNNAMED_6_CAPNP_I341_2: length 16.8
  BOTTOM w0.127: R254.1 77.19,63.57 74.74,66.01 70.11,66.01 68.46,64.36 U203.5
  BOTTOM w0.152: 69.65,65.55 69.53,65.67 R299.1
  BOTTOM w0.254: R252.2 67.4,67.21 C218.2 67.4,65.34 67.34,65.28 U203.5
UNNAMED_6_CAPNP_I345_1: length 23.4
  INTERNAL3 w0.254: v1(58.85,64.8) v1(58.85,59.19) ; v1(69.5,59.24) v1(69.5,61.11)
  BOTTOM w0.254: v1(69.5,59.24) 68.89,59.24 68.84,59.19 v1(58.85,59.19) ; C219.1 69.5,61.7 v1(69.5,61.11) ; C219.1 69.4,61.72 68.06,63.06 U203.7 ; C219.1 70.51,61.72 R253.1 ; R249.2 v1(58.85,64.8)
UNNAMED_6_CAPNP_I345_2: length 16.1
  BOTTOM w0.127: R255.1 77.61,62.7 74.59,65.71 70.23,65.71 68.78,64.26 68.78,63.78
  BOTTOM w0.152: 69.35,64.83 69.53,64.66 R300.2
  BOTTOM w0.254: R253.2 70.51,62.94 C219.2 69.48,62.94 68.71,63.71 ; 68.78,63.78 68.71,63.71 ; 68.71,63.71 U203.6
UNNAMED_6_CAPNP_I357_2: length 3.4
  BOTTOM w0.254: R250.2 60.24,64.58 60.42,64.4 60.42,64.31 60.5,64.24 60.58,64.24 C251.2 60.84,63.87 61,63.71 U203.3
UNNAMED_6_CAPNP_I359_2: length 3.2
  BOTTOM w0.254: R203.2 60.23,48.45 60.75,47.93 C200.2 61.21,47.56 U200.3
UNNAMED_6_CAPNP_I441_2: length 7.2
  BOTTOM w0.254: C252.2 81.5,68.9 R301.1 ; R302.2 82.36,69.84 R301.1 ; R301.1 81.46,69.88 81.46,71.05 81.48,71.07 81.48,73.72 81.58,73.83 U209.6
UNNAMED_6_EKCAPNP_I10_1: length 3.8
  BOTTOM w0.254: R202.1 59.88,47.72 C201.1 59.89,46.8 60.81,46.8 60.92,46.91 U200.2
UNNAMED_6_EKCAPNP_I10_2: length 1.2
  BOTTOM w0.254: R201.1 58.98,45.68 C201.2
UNNAMED_6_EKCAPNP_I203_2: length 2
  BOTTOM w0.254: U205.1 65.77,73.55 65.83,73.48 C223.2
UNNAMED_6_EKCAPNP_I214_2: length 3.6
  BOTTOM w0.254: U209.16 84.76,81.36 85.7,82.3 85.7,82.94 C237.2 86.59,82.96 R286.2
UNNAMED_6_EKCAPNP_I237_2: length 1.9
  TOP w0.381: C239.2 86.43,48.67 v2(86.54,48.56)
  BOTTOM w0.254: R212.1 86.26,48.47 86.36,48.56 v2(86.54,48.56)
  BOTTOM w0.381: v2(86.54,48.56) 87,48.56 Q200.8
UNNAMED_6_EKCAPNP_I261_2: length 2.3
  TOP w0.254: C240.2 v2(86.71,40.93)
  BOTTOM w0.254: v2(86.71,40.93) 86.6,40.82 86.42,40.82 86.29,40.7 R227.1
  BOTTOM w0.381: v2(86.71,40.93) 87.25,40.93 Q201.8
UNNAMED_6_EKCAPNP_I287_1: length 4
  BOTTOM w0.254: U201.2 61.09,36.34 60.83,36.08 59.9,36.08 C206.1 59.9,37.16 R223.1
UNNAMED_6_EKCAPNP_I287_2: length 1.2
  BOTTOM w0.254: C206.2 59.01,36.07 R222.1
UNNAMED_6_EKCAPNP_I298_2: length 1.9
  TOP w0.381: C241.2 86.61,33.56 v2(86.66,33.5)
  BOTTOM w0.254: R246.1 86.12,33.56 86.61,33.56 v2(86.66,33.5)
  BOTTOM w0.381: Q202.8 87.14,33.5 v2(86.66,33.5)
UNNAMED_6_EKCAPNP_I321_1: length 4.1
  BOTTOM w0.254: R236.1 59.79,29 C211.1 60.37,27.97 60.67,28.26 U202.2
UNNAMED_6_EKCAPNP_I321_2: length 1.1
  BOTTOM w0.254: C211.2 58.89,26.9 R235.1
UNNAMED_6_EKCAPNP_I332_2: length 2.5
  TOP w0.381: C242.2 86.18,61.39 v2(86.63,61.39)
  BOTTOM w0.254: R259.1 86,61.19 86.13,61.19 86.33,61.39 v2(86.63,61.39)
  BOTTOM w0.381: Q203.8 87.19,61.39 v2(86.63,61.39)
UNNAMED_6_EKCAPNP_I355_1: length 4
  BOTTOM w0.254: U203.2 61,63.06 60.85,62.91 59.79,62.91 C216.1 59.77,63.91 R249.1
UNNAMED_6_EKCAPNP_I355_2: length 1.2
  BOTTOM w0.254: C216.2 58.87,61.78 R248.1
UNNAMED_6_EKCAPNP_I377_1: length 3.6
  TOP w0.254: C270.1 48.27,88.69 47.6,88.01 U211.3
UNNAMED_6_EKCAPNP_I377_2: length 2
  TOP w0.254: U211.6 50.18,90.8 49.93,91.04 C270.2
UNNAMED_6_EKCAPNP_I423_2: length 2.7
  TOP w0.254: U211.5 51.81,88.96 C273.2 51.98,89.59 R289.2
UNNAMED_6_EKRESSMD_I42_1: length 15.5
  BOTTOM w0.127: R293.1 70.02,48.68 70.03,48.68 ; R207.1 77.31,49.93 76.06,48.68 70.03,48.68 ; U200.5 68.52,48.21 68.98,48.68 70.03,48.68
  BOTTOM w0.254: U200.5 67.4,49.05 67.46,49.1 67.46,50.84 67.44,50.85 ; 67.44,50.85 R206.2 ; 67.44,50.85 C204.2
UNNAMED_6_EKRESSMD_I42_2: length 12
  BOTTOM w0.127: R207.2 79.25,49.93 79.78,49.4 82.92,49.4 84.47,50.95 85.27,50.95 85.35,51.03 R211.1
  BOTTOM w0.889: R211.1 82.84,51.59 81.95,50.7 VIL_SBB0.1
UNNAMED_6_EKRESSMD_I43_1: length 14.4
  BOTTOM w0.127: 68.66,47.56 68.63,47.59 68.63,47.93 69.06,48.36 69.98,48.36 ; 69.98,48.36 69.98,48.36 R294.2 ; 69.98,48.36 76.23,48.36 77,49.14 R208.1
  BOTTOM w0.254: U200.6 68.66,47.56 68.67,47.55 68.94,47.55 69.5,46.98 C203.2 69.99,47.11 70.7,47.11 R205.2
UNNAMED_6_EKRESSMD_I99_1: length 4.2
  BOTTOM w0.254: 60.81,45.58 60.9,45.58 61.23,45.91 61.23,45.99 61.49,46.26 U200.1 ; 60.81,45.58 60.72,45.67 R201.2 ; 60.81,45.58 60.69,45.46 R204.1
UNNAMED_6_EKRESSMD_I99_2: length 46.5
  INTERNAL3 w0.254: v1(59.17,44.6) 59.17,45.21 59.21,45.24 v1(59.21,55.15)
  BOTTOM w0.254: v1(59.21,55.15) 75.3,55.15 75.98,55.83 88.56,55.83 89.88,54.52 92.45,54.52 92.46,54.51 J200.1 ; R204.2 v1(59.17,44.6)
UNNAMED_6_EKRESSMD_I207_1: length 1.6
  BOTTOM w0.254: U205.14 65.77,82.56 R214.1
UNNAMED_6_EKRESSMD_I222_2: length 1.6
  BOTTOM w0.254: R283.2 64.48,80.96 U205.12
UNNAMED_6_EKRESSMD_I273_2: length 11.7
  BOTTOM w0.127: R233.1 85.34,42.76 85.25,42.68 84.49,42.68 83.36,41.55 80.35,41.55 79.08,42.83 78.76,42.83 R229.2
  BOTTOM w0.889: VIL_SBB1.1 83.52,42.81 84.04,43.33 R233.1
UNNAMED_6_EKRESSMD_I278_1: length 4.4
  BOTTOM w0.254: R225.1 59.89,34.89 R222.2 60.79,34.91 60.83,34.86 62.44,34.86 62.66,35.08 U201.1
UNNAMED_6_EKRESSMD_I278_2: length 62.4
  INTERNAL3 w0.254: J202.1 92.7,40.14 92.7,40.02 92.56,39.88 92.56,24.52 v1(92.1,24.06) ; v1(58.3,34.01) v1(58.3,24.06)
  BOTTOM w0.254: v1(58.3,24.06) v1(92.1,24.06) ; R225.2 v1(58.3,34.01)
UNNAMED_6_EKRESSMD_I306_2: length 12.1
  BOTTOM w0.127: R245.1 85.6,36.38 85.6,35.84 85.51,35.75 84.97,35.75 84.96,35.74 84.95,35.74 83.55,34.34 80.47,34.34 79.43,35.38 R242.2
  BOTTOM w0.889: R245.1 83.27,36.41 VIL_SBB2.1
UNNAMED_6_EKRESSMD_I313_1: length 4.1
  BOTTOM w0.254: U202.1 61.32,27.61 60.55,26.84 R235.2 59.78,26.77 R238.1
UNNAMED_6_EKRESSMD_I313_2: length 39.2
  BOTTOM w0.254: R238.2 58.88,25.65 59.19,25.33 93.19,25.33 93.98,26.13 93.98,28.14 93.94,28.19 J204.1
UNNAMED_6_EKRESSMD_I340_2: length 10.6
  BOTTOM w0.127: R258.1 85.22,63.85 85.07,63.7 83.9,63.7 83.26,63.07 80.28,63.07 79.78,63.57 R254.2
  BOTTOM w0.889: VIL_LDO.1 83.81,64.73 84.14,64.4 R258.1
UNNAMED_6_EKRESSMD_I347_1: length 4.3
  BOTTOM w0.254: U203.1 61.92,61.69 59.84,61.69 R248.2 59.76,60.78 R251.1
UNNAMED_6_EKRESSMD_I347_2: length 47.1
  INTERNAL3 w0.254: J206.1 94.03,60.86 94.04,60.85 94.04,57.18 94.03,57.18 v1(94.03,56.57) ; v1(58.2,60.72) v1(58.2,55.96)
  BOTTOM w0.254: v1(58.2,55.96) 75.27,55.96 75.88,56.57 v1(94.03,56.57) ; R251.2 v1(58.2,60.72)
UNNAMED_6_EKRESSMD_I439_1: length 11
  BOTTOM w0.254: AIN1.1 87.58,68.83 86.61,69.81 R302.1
UNNAMED_6_EKRESSMD_I450_2: length 1.5
  BOTTOM w0.203: U205.10 63.17,82.35 R305.2
UNNAMED_6_EKRESSMD_I451_2: length 2.7
  BOTTOM w0.203: U205.11 63.82,82.51 63.08,83.25 R306.2
UNNAMED_6_EKRESSMD_I452_2: length 8.6
  INTERNAL3 w0.203: v1(83.49,82.01) v1(83.49,88.29)
  BOTTOM w0.203: v1(83.49,88.29) 82.56,88.29 R303.2 ; U209.14 v1(83.49,82.01)
UNNAMED_6_EKRESSMD_I453_2: length 6.9
  INTERNAL3 w0.203: v1(82.85,81.99) v1(82.85,87)
  BOTTOM w0.203: v1(82.85,87) 82.85,87.12 R304.2 ; U209.13 v1(82.85,81.99)
UNNAMED_6_HEADER2P_I444_2: length 5.3
  BOTTOM w0.254: Q201.4 89.81,43.97 90.24,44.4 90.53,44.4 90.53,44.39 R231.2 92.19,44.39 92.73,43.85 93.99,43.85 93.96,43.82 J202.2
UNNAMED_6_HEADER2P_I446_2: length 9.6
  INTERNAL3 w0.254: 93.98,31.87 93.94,31.91 J204.2
  INTERNAL3 w0.381: 93.98,31.87 93.98,35.93 93.92,35.98 v2(93.92,36.66)
  BOTTOM w0.508: v2(93.92,36.66) R244.2 92.14,36.66 92.03,36.76 Q202.4
UNNAMED_6_HEADER2P_I448_2: length 4.8
  BOTTOM w0.254: Q203.4 90.3,64.72 90.35,64.77 R257.2 92.71,64.77 92.79,64.7 94.04,64.7 94.03,64.68 J206.2
UNNAMED_6_RESSMD_I28_2: length 5.4
  BOTTOM w0.254: Q200.4 89.97,51.8 90.08,51.9 R210.2 91.52,51.9 91.59,51.98 94.06,51.98 94.05,51.97 J200.2
UNNAMED_6_RESSMD_I225_1: length 12
  BOTTOM w0.254: AIN7.1 82.97,84.91 82.21,84.15 R281.1
UNNAMED_6_RESSMD_I363_2: length 4.3
  BOTTOM w0.254: R288.2 88.45,82.07 89.18,81.33 Q205.1 90.17,80.63 90.11,80.57 Q206.3
VADC: length 14.7
  INTERNAL3 w0.508: v1(87.53,82.17) 86.87,81.52 v2(86.87,72.56)
  BOTTOM w0.254: Q205.2 88.66,83.23 R288.1 88.39,82.96 R286.1
  BOTTOM w0.381: v1(87.53,82.17) 87.53,82.93 R286.1
  BOTTOM w0.508: R277.1 v2(86.87,72.56)
VIO: length 187.1
  TOP w0.152: R10.2 v2(10.06,27.92)
  TOP w0.254: R107.1 v2(20.72,79) ; R17.2 36.77,69.51 v2(36.78,69.52) ; v2(30.2,75.49) 30.53,75.49 30.56,75.46 ; C120.2 22.21,82.91 22.93,82.18 U107.12 21.17,81.81 v2(20.72,81.36) 20.14,81.36 R108.1 ; v2(36.78,75.46) 30.56,75.46 ; 30.56,75.46 25.21,75.46 25.18,75.49 R143.1 23.92,75.49 23.82,75.39 v2(20.72,75.39) 20.67,75.44 R14.2 ; J2.1 9.74,42.28 v2(10.08,41.94)
  INTERNAL3 w0.152: 10.06,27.91 v2(10.06,27.92)
  INTERNAL3 w0.254: v2(10.08,41.94) 10.08,41.68 10.06,41.66 ; 10.06,41.66 10.06,27.91 ; 10.06,41.66 v2(10.06,69.6) ; J4.1 9.35,13.8 9.36,13.81 J3.1 9.36,27.22 v2(10.06,27.92) ; v2(20.72,81.36) v2(20.72,79) v2(20.72,75.39) ; v2(36.78,69.52) v2(36.78,75.46) ; v2(30.2,75.49) v2(30.2,92.43)
  BOTTOM w0.254: v2(36.78,69.52) 36.17,69.52 36.1,69.6 v2(10.06,69.6)
  BOTTOM w0.381: v2(30.2,92.43) 60.27,92.43 J101.5 J101.3 J101.1
VL: length 39.1
  TOP w0.203: v3(44.85,41.48) 45.27,41.05 U1.D1
  TOP w0.254: v2(11.93,40.5) 12.54,40.5 12.55,40.49 22.75,40.49 22.76,40.49 39.76,40.49 v2(40.26,41)
  INTERNAL2 w0.254: v3(44.85,41.48) v4(45.29,41.48)
  INTERNAL3 w0.254: v2(40.26,41) 41.43,41 41.91,41.48 v4(45.29,41.48) ; VL.1 v2(11.93,40.5)
VLDO: length 27.1
  INTERNAL3 w0.152: v1(81.58,82.06) 81.58,71.63 83.86,69.36 v1(83.86,61.04)
  BOTTOM w0.152: U209.11 v1(81.58,82.06)
  BOTTOM w0.254: v1(81.58,82.06) 81.58,82.59 81.38,82.79 81.33,82.79 80.86,83.26 R260.1 80.87,83.32 C220.2 ; R259.2 84.95,61.04 v1(83.86,61.04)
VSBB0: length 34.4
  INTERNAL3 w0.254: v1(80.04,66.91) 80.04,72.56 80.36,72.88 v1(80.36,73.64) ; v1(84.36,48.47) v1(84.36,66.91)
  BOTTOM w0.254: R212.2 84.88,48.49 84.38,48.49 v1(84.36,48.47) ; C205.2 78.54,74.97 R213.1 79.05,75.04 79.09,75.08 U209.8 80.36,75.03 v1(80.36,73.64) ; v1(84.36,66.91) v1(80.04,66.91)
VSBB1: length 47.5
  INTERNAL3 w0.254: v1(80.18,40.81) 80.18,61.62 79.49,62.31 v1(79.49,80.68)
  BOTTOM w0.152: v1(80.18,40.81) 80.74,40.81 80.9,40.97 83.21,40.97 83.48,40.7 R227.2
  BOTTOM w0.254: C210.2 78.76,79.83 R234.1 79.48,80.69 v1(79.49,80.68) U209.9
VSBB2: length 57.5
  INTERNAL3 w0.152: v1(80.95,82.36) 80.95,71.66 83.41,69.19 83.36,61.21 83.36,33.62 83.56,33.42 v1(83.56,32.87)
  BOTTOM w0.254: v1(83.56,32.87) 84.19,33.5 R246.2 ; U209.10 v1(80.95,82.36) 79.82,82.36 79.36,81.91 R247.1 78.89,82.02 78.89,82.72 C215.2
VSYS: length 118.6
  TOP w0.152: 46.49,40.49 U1.E2
  TOP w0.254: R2.2 v2(7.12,58.13) ; C11.1 45.25,39.25 46.49,40.49
  TOP w0.508: v2(7.12,58.13) 6.26,58.13 2.97,61.42 2.97,63.39 2.32,64.04 SW2.1 ; R9.1 v2(57.45,54.35)
  INTERNAL2 w0.381: v3(45.13,39.38) 45.15,39.38 v4(45.43,39.66)
  INTERNAL3 w0.508: v2(7.12,58.13) 7.1,58.15 v2(7.1,9.75)
  BOTTOM w0.508: VSYS.1 55.12,8.64 32.87,8.64 31.75,9.75 v2(7.1,9.75)
  vias: v1(46.65,42.26) v1(46.66,41.73) v1(46.67,41.17) v1(47.24,42.26) v3(44.55,39.37) v3(44.83,39.37) v3(44.95,39.1) v4(44.63,38.91)
VUSB: length 317.2
  TOP w0.152: C224.1 77.4,6.44 77.4,7.26 77.53,7.4 U206.C2
  TOP w0.254: 12.34,71.36 11.22,71.36 10.95,71.63 FB100.2 7.75,71.6 C154.2 7.78,70.51 R115.1 ; 12.34,71.36 12.41,71.29 C108.2 ; 12.34,71.36 12.51,71.52 U101.19 ; C112.2 39.35,86.56 U104.1 39.27,86.64 39.27,87.48 39.45,87.66 40.39,87.66 40.61,87.43 U104.3 ; C110.2 32.73,85.22 U103.1 32.69,86.69 32.69,87.57 32.95,87.83 33.77,87.83 34.03,87.57 U103.3 ; C118.2 26.79,85.27 U102.1 26.75,86.64 26.75,87.48 26.93,87.66 27.79,87.66 28.09,87.35 U102.3
  TOP w0.381: R115.1 v2(7.78,68.68) ; C118.2 26.74,85.21 v2(26.74,84.09) ; C224.1 v2(72.68,6.29) ; C112.2 39.35,84.46 38.98,84.09 ; 32.87,84.09 32.72,84.24 C110.2
  TOP w0.508: v2(26.74,84.09) v2(43.5,84.09)
  INTERNAL3 w0.508: J100.1 43.56,92.21 43.5,92.16 v2(43.5,84.09) ; v2(26.72,68.68) 26.72,69.42 26.74,69.44 v2(26.74,84.09) ; v2(66.84,15.65) v1(66.84,26.44) v1(66.84,34.47) v1(66.84,45.16) v1(66.84,61.25) ; v2(91.97,83.11) 90.73,84.35 v2(90.73,86.03) ; v2(72.68,6.29) v2(72.68,15.58)
  INTERNAL3 w1.27: J10.2 32.97,15.37 29.97,18.37 v1(29.97,68.68)
  BOTTOM w0.254: v1(66.84,34.47) 66.94,34.57 C207.1 67.36,34.58 U201.8 ; U207.5 U207.6 76.1,15.53 C226.1 ; U203.8 67.34,61.39 C217.1 67.39,61.25 v1(66.84,61.25) ; U202.8 67.4,27.61 67.4,26.48 C212.1 v1(66.84,26.44) ; v1(66.84,45.16) 66.9,45.22 C202.1 67.4,45.23 U200.8
  BOTTOM w0.381: v2(72.68,15.58) 73.36,15.58 73.38,15.55 C226.1 ; Q206.1 92.31,80.07 R287.1
  BOTTOM w0.508: v2(72.68,15.58) 68.66,15.58 68.59,15.65 v2(66.84,15.65) 57.63,15.65 55.8,17.48 35.03,17.48 32.95,15.39 32.97,15.37 J10.2 ; Q206.1 92.31,80.92 92.37,80.98 Q205.3 91.97,82.68 v2(91.97,83.11) ; v2(90.73,86.03) 82.14,86.03 81.66,85.55 44.96,85.55 v2(43.5,84.09)
  BOTTOM w1.016: v1(29.97,68.68) v2(26.72,68.68) v2(7.78,68.68)

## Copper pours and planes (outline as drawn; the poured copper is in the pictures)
VBATT on TOP: 48.51,3.89 48.51,12.62 44.15,12.62 44.15,7.49 45.42,6.22 45.42,3.86 48.49,3.86
VBATT on INTERNAL2: 46.35,39.8 46.1,39.8 45.44,39.14 45.44,38.89 45.24,38.68 45.39,38.4 45.67,38.4 45.9,38.76 46.3,38.76 46.5,38.95 46.5,39.25 46.35,39.4
VBATT on INTERNAL3: 45.42,39.22 46.27,39.21 46.3,39.25 46.3,26.85 46.27,26.82 48.76,24.32 48.78,23.9 48.78,16.81 48.77,12.29 48.77,7.52 48.26,6.91 48.26,3.68 43.56,3.71 43.59,9.55 43.63,34.37 44.48,35.21 44.5,38.2
BST on TOP: 50.42,38.99 50.42,37.34 51.31,37.34 51.31,38.99
CHGIN on TOP: 44.48,40.77 45.69,40.77 45.95,40.51 45.95,40.44 45.52,40.01 44.48,40.01
CHGIN on INTERNAL2: 44.32,40.74 45.26,40.74 45.29,40.72 45.29,40.23 44.73,39.67 43.66,39.67 43.66,40.08
CHGIN on INTERNAL3: 34.49,9.47 34.54,37.19 36.68,39.32 42.37,39.32 43.26,40.21 44.7,40.21 44.7,39.73 42.16,37.19 42.16,9.45
GROUND on TOP: 0.91,0.46 0.89,12.91 0.89,51.27 0.86,95.28 0.89,95.28 0.89,95.94 95.38,95.94 95.38,0.46 ; 17 cut-outs
GROUND on BOTTOM: 94.76,94.92 94.99,95.11 94.95,52.77 94.88,52.78 94.82,52.75 94.14,52.4 93.39,52.56 93.11,52.28 93.09,52.17 93.18,52.11 94.95,52.11 95.2,0.91 6.5,0.81 6.5,5.49 4.57,7.32 1.63,7.32 1.78,96.01 95,96.01 95,95.52 95,96.01 93.77,96.01 93.68,95.92 93.74,95.82 94.2,95.55 94.56,95.15 ; 40 cut-outs
GROUND on INTERNAL2: 7.01,0.81 7.01,5.49 5.08,7.42 0.91,7.42 0.8,96.27 95.67,96.27 95.61,0.81 ; 1 cut-out
IBATT_SNS on BOTTOM: 56.01,4.57 56.01,4.58 48.55,4.58 48.55,7.21 48.64,7.3 56.41,7.27 61.47,12.32 63.75,12.32 66.41,9.66 72.53,9.66 74.52,9.65 75.17,9 75.19,8.09 73.71,8.09 73.26,7.64 72.52,7.64 72.52,7.62 69.47,4.57
IN_SBB on TOP: 49.28,14.73 49.35,9.47 53.24,9.47 53.21,14.73
IN_SBB on BOTTOM: 46.76,40.31 46.76,39.12 47.88,39.12 47.88,40.31
IN_SBB on INTERNAL2: 46.87,40.21 46.87,40.17 46.54,39.84 46.54,39.46 46.96,39.04 47.18,39.04 47.43,39.29 47.43,39.85 47.07,40.21 46.87,40.21
IN_SBB on INTERNAL3: 49.38,9.55 49.4,24.13 46.48,27.05 46.48,39.88 46.86,40.26 47.37,40.26 47.38,40.25 47.41,40.25 48.13,39.53 48.13,39.5 48.13,39.5 48.13,34.29 53.21,29.21 53.24,9.55
LDO on TOP: 72.9,60.2 72.9,58.93 75.82,58.93 75.82,60.2
LXA on TOP: 46.48,34.8 46.48,37.47 46.58,37.62 46.99,38.02 46.99,38.48 47.75,38.48 47.75,35.31 47.24,34.8
LXB on TOP: 49.02,34.8 48.51,35.31 48.51,38.61 49.91,38.61 49.91,34.8
SBB0 on TOP: 53.57,42.04 56.34,42.04 59.33,45.01 86.66,45.01 86.66,47.65 57.51,47.65 53.64,43.79 52.88,43 51.79,41.91 53.42,41.88
SBB1 on TOP: 53.85,41.05 53.87,40.34 56.54,37.69 86.66,37.69 86.66,39.93 86.46,40.13 58.52,40.13 57,41.66 54.46,41.66
SBB2 on TOP: 51.59,40.31 51.59,38.53 60.55,29.57 86.56,29.57 86.77,29.77 86.77,32.61 61.26,32.61 54.25,39.62 53.54,39.62 52.73,40.31
UNNAMED_2_MAX14689_I1_NC1 on BOTTOM: 73.78,7.43 75.19,7.42 77.05,5.57 78.95,5.57 78.96,5.41 78.96,4.22 78.92,4.18 74.13,4.18 73.77,4.54 73.78,5.8
UNNAMED_6_EKCAPNP_I237_2 on BOTTOM: 87,45.09 91.77,45.06 91.77,50.85 87,50.88
UNNAMED_6_EKCAPNP_I261_2 on BOTTOM: 87.09,41.27 87.09,37.8 91.8,37.77 91.8,41.27 90.55,42.49 90.53,43.08 87.1,43.08
UNNAMED_6_EKCAPNP_I298_2 on BOTTOM: 87.12,35.92 87.11,30.45 91.69,30.45 91.72,35.92
UNNAMED_6_EKCAPNP_I332_2 on BOTTOM: 87.38,62.1 87.38,57.78 90.93,57.81 90.98,63.73 87.4,63.73
UNNAMED_6_EKRESSMD_I42_2 on BOTTOM: 88.65,51.44 86.61,51.44 86.23,51.05 84.84,51.05 84.84,52.2 85.34,52.7 88.65,52.7
UNNAMED_6_EKRESSMD_I273_2 on BOTTOM: 88.65,44.45 88.65,43.56 86.74,43.56 86.08,42.89 84.96,42.89 84.96,44.07 85.34,44.45
UNNAMED_6_EKRESSMD_I306_2 on BOTTOM: 88.77,36.32 86.87,36.32 86.5,35.96 85.21,35.95 85.22,37.21 88.77,37.21
UNNAMED_6_EKRESSMD_I340_2 on BOTTOM: 84.84,63.88 85.98,63.88 86.36,64.26 88.9,64.26 88.9,65.66 85.22,65.66 84.84,65.28
VSYS on BOTTOM: 46.23,40.97 47.8,40.97 47.8,42.04 47.37,42.44 46.23,42.44
VSYS on INTERNAL2: 44.42,39.5 44.86,39.5 45.24,39.88 45.67,39.88 45.67,39.62 45.19,39.14 45.19,38.84 45.03,38.68 44.42,38.68
VSYS on INTERNAL3: 53.75,9.65 53.72,18.37 53.72,29.78 48.32,35.17 48.32,39.62 47.45,40.49 46.91,40.49 45.83,39.41 45.83,39.4 45.36,39.4 44.55,38.58 44.27,38.58 44.27,39.01 45.03,39.78 45.06,39.78 45.06,39.9 45.26,40.11 46.34,41.19 46.34,43.11 49.07,45.85 49.12,55.08 49.06,55.15 49.06,55.24 49.47,55.65 57.53,55.65 60.07,53.11 60.05,9.65 ; 2 cut-outs

Small or netless copper shapes (teardrops, artwork), in the pictures only: 6 on TOP, 5 on INTERNAL2

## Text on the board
Ref Des/Silkscreen Top: SCL | SDA | GND | nIRQ | nRST | VIO | AMUX | GPIO | nEN | PWRHLD | SW2 | SW1 | THERMISTOR | VUSB | CHGIN | LDO | 3.3V | 1.8V | IBATT_SNS | 4 | 1 | 3 | 2 | www.maximintegrated.com | 1-408-601-1000 | LB 12/16 | MAX77651 EV KIT | REVA
